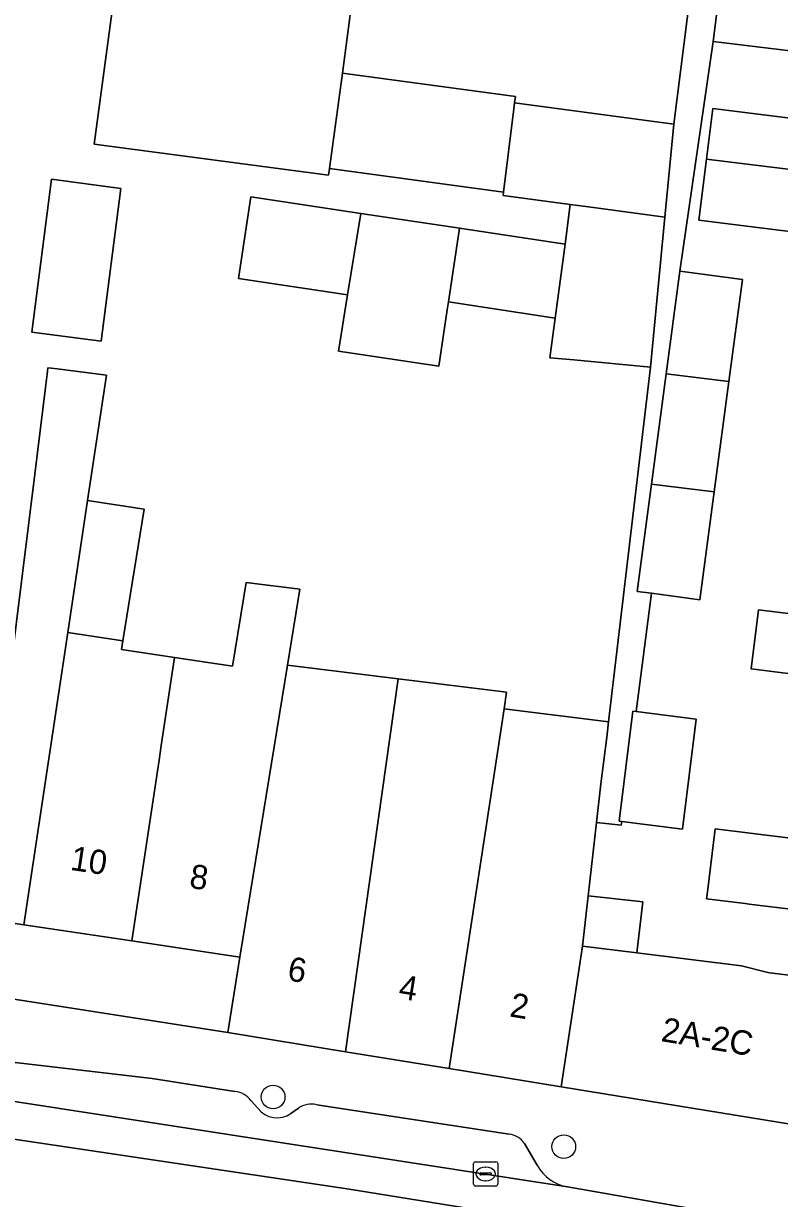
# Model space of a CAD drawing. Extents: x 162172 to 163187, y 382874 to 383685.
# Drawn here: x 162672.8 to 162704, y 383324.93 to 383373.42 of the extents above; entities that cross this region are included whole.
import ezdxf

# ---------------------------------------------------------------- set-up
doc = ezdxf.new("R2010")
doc.units = 0
for name, color, linetype in [('IMGEO_Boom', 7, 'Continuous'), ('IMGEO_Erf', 7, 'Continuous'), ('IMGEO_Kolk', 7, 'Continuous'), ('IMGEO_Pand', 7, 'Continuous'), ('IMGEO_Pand_nummerreeks', 7, 'Continuous'), ('IMGEO_Parkeervlak_open', 7, 'Continuous'), ('IMGEO_Rijbaan_lokaal_gesloten', 7, 'Continuous'), ('IMGEO_Voetpad_open', 7, 'Continuous')]:
    doc.layers.add(name, color=color, linetype=linetype)

msp = doc.modelspace()

# ---------------------------------------------------------------- linework, layer by layer
at = {"layer": 'IMGEO_Boom'}
for centre in [(162683.101, 383329.122), (162695.098, 383327.073)]:
    msp.add_circle(centre, 0.489, dxfattribs=at)
at = {"layer": 'IMGEO_Erf'}
for points in [[(162686.382, 383374.516), (162685.957, 383371.365), (162693.103, 383370.401), (162693.069, 383370.149), (162699.635, 383369.263), (162703.655, 383401.01)], [(162672.244, 383346.619), (162673.262, 383354.819), (162673.706, 383358.396), (162673.775, 383358.952), (162673.807, 383359.209), (162673.954, 383359.191), (162674.187, 383359.162), (162676.222, 383358.91), (162675.443, 383353.731), (162677.778, 383353.38), (162676.899, 383347.94), (162676.843, 383347.588), (162679.03, 383347.259), (162681.428, 383346.899), (162681.989, 383350.35), (162684.2, 383350.076), (162683.69, 383346.942), (162688.256, 383346.377), (162692.738, 383345.821), (162692.634, 383345.142), (162696.946, 383344.607), (162698.677, 383359.232), (162695.514, 383359.534), (162694.528, 383359.628), (162694.745, 383361.264), (162690.335, 383361.927), (162690.286, 383361.6), (162689.937, 383359.278), (162685.799, 383359.901), (162686.176, 383362.219), (162681.666, 383362.897), (162682.173, 383366.265), (162686.722, 383365.581), (162690.793, 383364.969), (162695.15, 383364.314), (162695.367, 383365.95), (162692.593, 383366.322), (162692.61, 383366.459), (162685.425, 383367.428), (162685.388, 383367.153), (162675.713, 383368.44), (162676.707, 383375.803)], [(162704.444, 383372.285), (162701.266, 383372.681), (162699.889, 383363.201), (162702.479, 383362.855), (162701.917, 383358.645), (162701.309, 383354.088), (162700.716, 383349.639), (162698.724, 383349.905), (162698.085, 383345.025), (162700.562, 383344.718), (162699.999, 383340.178), (162697.49, 383340.489), (162697.471, 383340.34), (162696.452, 383340.455), (162696.109, 383337.425), (162698.356, 383337.171), (162698.119, 383335.067), (162702.438, 383334.532), (162703.526, 383334.261), (162703.606, 383334.251), (162704.721, 383334.113)], [(162707.625, 383364.439), (162700.678, 383365.299), (162700.991, 383367.821), (162701.249, 383369.907), (162708.196, 383369.046)], [(162705.449, 383346.46), (162702.837, 383346.784), (162703.139, 383349.225), (162705.482, 383348.935)], [(162625.697, 383340.429), (162681.225, 383331.781), (162681.73, 383334.89), (162677.27, 383335.561), (162672.811, 383336.231), (162668.35, 383336.902)], [(162704.802, 383336.825), (162702.75, 383337.08), (162702.589, 383337.1), (162700.988, 383337.299), (162701.024, 383337.584), (162701.346, 383340.184), (162704.35, 383339.812)]]:
    msp.add_lwpolyline(points, dxfattribs=at)
msp.add_lwpolyline([(162675.996, 383360.304), (162673.135, 383360.677), (162673.958, 383366.988), (162676.819, 383366.615)], close=True, dxfattribs=at)
at = {"layer": 'IMGEO_Kolk'}
for p, q in [((162691.372, 383325.523), (162691.372, 383326.375)), ((162691.447, 383326.449), (162692.299, 383326.449)), ((162691.86, 383326.229), (162691.885, 383326.229)), ((162692.373, 383326.375), (162692.373, 383325.523)), ((162691.631, 383325.943), (162691.631, 383325.955)), ((162692.069, 383325.906), (162691.671, 383325.906)), ((162691.674, 383325.992), (162692.072, 383325.992)), ((162691.883, 383325.669), (162691.858, 383325.669)), ((162692.115, 383325.955), (162692.115, 383325.943)), ((162692.299, 383325.449), (162691.447, 383325.449))]:
    msp.add_line(p, q, dxfattribs=at)
for points in [[(162691.372, 383325.523), (162691.372, 383326.375)], [(162691.447, 383326.449), (162692.299, 383326.449)], [(162692.373, 383326.375), (162692.373, 383325.523)], [(162692.299, 383325.449), (162691.447, 383325.449)]]:
    msp.add_lwpolyline(points, dxfattribs=at)
for centre, radius, start, end in [((162691.449, 383326.373), 0.0765, 91.552, 178.448), ((162691.449, 383326.373), 0.0765, 91.552, 178.448), ((162692.297, 383326.373), 0.0765, 1.552, 88.448), ((162692.297, 383326.373), 0.0765, 1.552, 88.448), ((162691.671, 383325.952), 0.0403, 85.8775, 175.7526), ((162691.668, 383325.942), 0.0366, 178.938, 274.7102), ((162692.072, 383325.949), 0.043, 264.8664, 352.4533), ((162692.076, 383325.954), 0.0386, 1.7309, 96.639), ((162691.449, 383325.525), 0.0765, 181.552, 268.448), ((162691.449, 383325.525), 0.0765, 181.552, 268.448), ((162692.297, 383325.525), 0.0765, 271.552, 358.448), ((162692.297, 383325.525), 0.0765, 271.552, 358.448)]:
    msp.add_arc(centre, radius, start, end, dxfattribs=at)
for centre, major_axis, ratio, start_param, end_param in [((162691.859, 383325.949), (-0.387, 0.002), 0.722429, 4.712389, 7.853982), ((162691.884, 383325.949), (-0.39, 0.002), 0.717154, 1.570796, 4.712389)]:
    msp.add_ellipse(centre, major_axis=major_axis, ratio=ratio, start_param=start_param, end_param=end_param, dxfattribs=at)
at = {"layer": 'IMGEO_Pand'}
for points in [[(162705.022, 383376.787), (162701.827, 383377.183), (162701.266, 383372.681), (162704.444, 383372.285)], [(162686.382, 383374.516), (162676.707, 383375.803), (162675.713, 383368.44), (162685.388, 383367.153), (162685.425, 383367.428), (162685.957, 383371.365)], [(162693.035, 383369.894), (162693.069, 383370.149), (162693.103, 383370.401), (162685.957, 383371.365), (162685.425, 383367.428), (162692.61, 383366.459)], [(162699.635, 383369.263), (162693.069, 383370.149), (162693.035, 383369.894), (162692.61, 383366.459), (162692.593, 383366.322), (162695.367, 383365.95), (162696.118, 383365.849), (162699.269, 383365.427)], [(162708.196, 383369.046), (162701.249, 383369.907), (162700.991, 383367.821), (162707.937, 383366.96)], [(162707.937, 383366.96), (162700.991, 383367.821), (162700.678, 383365.299), (162707.625, 383364.439)], [(162676.819, 383366.615), (162673.958, 383366.988), (162673.135, 383360.677), (162675.996, 383360.304)], [(162686.176, 383362.219), (162686.722, 383365.581), (162682.173, 383366.265), (162681.666, 383362.897)], [(162699.269, 383365.427), (162696.118, 383365.849), (162695.367, 383365.95), (162695.15, 383364.314), (162694.745, 383361.264), (162694.528, 383359.628), (162695.514, 383359.534), (162698.677, 383359.232)], [(162690.793, 383364.969), (162686.722, 383365.581), (162686.176, 383362.219), (162685.799, 383359.901), (162689.937, 383359.278), (162690.286, 383361.6), (162690.335, 383361.927)], [(162690.793, 383364.969), (162690.335, 383361.927), (162694.745, 383361.264), (162695.15, 383364.314)], [(162701.917, 383358.645), (162702.479, 383362.855), (162699.889, 383363.201), (162699.324, 383358.966)], [(162674.624, 383348.282), (162675.443, 383353.731), (162676.222, 383358.91), (162674.187, 383359.162), (162673.954, 383359.191), (162673.807, 383359.209), (162673.775, 383358.952), (162673.706, 383358.396), (162673.262, 383354.819), (162672.244, 383346.619), (162671.969, 383346.653), (162669.856, 383346.915), (162669.592, 383345.16), (162669.553, 383344.9), (162668.35, 383336.902), (162672.811, 383336.231)], [(162701.917, 383358.645), (162699.324, 383358.966), (162698.716, 383354.41), (162701.309, 383354.088)], [(162701.309, 383354.088), (162698.716, 383354.41), (162698.125, 383349.985), (162698.724, 383349.905), (162700.716, 383349.639)], [(162675.443, 383353.731), (162674.624, 383348.282), (162676.899, 383347.94), (162677.778, 383353.38)], [(162683.69, 383346.942), (162684.2, 383350.076), (162681.989, 383350.35), (162681.428, 383346.899), (162679.03, 383347.259), (162678.484, 383343.629), (162678.392, 383343.018), (162677.27, 383335.561), (162681.73, 383334.89)], [(162705.752, 383348.902), (162705.482, 383348.935), (162703.139, 383349.225), (162702.837, 383346.784), (162705.449, 383346.46)], [(162679.03, 383347.259), (162676.843, 383347.588), (162676.899, 383347.94), (162674.624, 383348.282), (162672.811, 383336.231), (162677.27, 383335.561), (162678.392, 383343.018), (162678.484, 383343.629)], [(162687.76, 383342.866), (162688.256, 383346.377), (162683.69, 383346.942), (162681.73, 383334.89), (162681.225, 383331.781), (162686.082, 383330.991)], [(162692.538, 383344.51), (162692.634, 383345.142), (162692.738, 383345.821), (162688.256, 383346.377), (162687.76, 383342.866), (162686.082, 383330.991), (162690.373, 383330.294)], [(162696.109, 383337.425), (162696.452, 383340.455), (162696.631, 383342.038), (162696.871, 383343.972), (162696.946, 383344.607), (162692.634, 383345.142), (162692.538, 383344.51), (162690.373, 383330.294), (162694.994, 383329.543), (162695.874, 383335.345)], [(162698.085, 383345.025), (162697.944, 383345.042), (162697.382, 383340.502), (162697.49, 383340.489), (162699.999, 383340.178), (162700.562, 383344.718)], [(162718.231, 383338.092), (162704.35, 383339.812), (162701.346, 383340.184), (162701.024, 383337.584), (162700.988, 383337.299), (162702.589, 383337.1), (162702.75, 383337.08), (162704.802, 383336.825), (162704.5, 383334.393), (162704.751, 383334.352), (162705.436, 383334.24), (162713.487, 383332.918), (162718.117, 383337.17)], [(162696.109, 383337.425), (162695.874, 383335.345), (162698.119, 383335.067), (162698.356, 383337.171)], [(162704.751, 383334.352), (162704.721, 383334.113), (162703.606, 383334.251), (162703.526, 383334.261), (162702.438, 383334.532), (162698.119, 383335.067), (162695.874, 383335.345), (162694.994, 383329.543), (162707.584, 383327.496), (162713.487, 383332.918), (162705.436, 383334.24)]]:
    msp.add_lwpolyline(points, close=True, dxfattribs=at)
at = {"layer": 'IMGEO_Parkeervlak_open'}
for points in [[(162681.525, 383329.352), (162678.105, 383329.885), (162671.858, 383330.613), (162670.982, 383330.717), (162670.498, 383330.752)], [(162667.234, 383329.74), (162695.256, 383325.416)], [(162682.469, 383328.656), (162682.19, 383328.964)], [(162684.143, 383328.656), (162683.834, 383328.444)], [(162692.84, 383327.592), (162684.899, 383328.802)], [(162693.997, 383326.305), (162693.476, 383327.202)]]:
    msp.add_lwpolyline(points, dxfattribs=at)
for centre, radius, start, end in [((162681.424, 383328.415), 0.942, 35.6204, 83.856), ((162683.263, 383329.267), 1.001, 217.5668, 304.7769), ((162684.675, 383327.93), 0.9, 75.6064, 126.2545), ((162692.71, 383326.667), 0.934, 34.9515, 82.0146), ((162695.567, 383327.192), 1.803, 209.4704, 260.0765)]:
    msp.add_arc(centre, radius, start, end, dxfattribs=at)
at = {"layer": 'IMGEO_Rijbaan_lokaal_gesloten'}
for points in [[(162701.209, 383324.364), (162695.256, 383325.416), (162667.234, 383329.74), (162654.358, 383331.729), (162650.713, 383332.282), (162613.69, 383338.058), (162613.319, 383338.115), (162605.204, 383339.371), (162601.788, 383339.9), (162574.971, 383344.078), (162574.184, 383344.194), (162573.598, 383344.329), (162573.305, 383344.396)], [(162759.102, 383279.436), (162751.245, 383288.934), (162744.614, 383296.969), (162741.887, 383300.164), (162738.772, 383303.437), (162735.656, 383306.164), (162728.412, 383311.307), (162722.803, 383314.892), (162719.766, 383316.606), (162716.105, 383318.242), (162707.381, 383321.359), (162706.089, 383321.777), (162704.23, 383322.378), (162698.267, 383323.385), (162686.155, 383325.334), (162667.305, 383328.139), (162627.21, 383334.45)], [(162627.21, 383334.45), (162667.305, 383328.139), (162686.155, 383325.334), (162698.267, 383323.385), (162704.23, 383322.378), (162706.089, 383321.777), (162707.381, 383321.359), (162716.105, 383318.242), (162719.766, 383316.606), (162722.803, 383314.892), (162728.412, 383311.307), (162735.656, 383306.164), (162738.772, 383303.437), (162741.887, 383300.164), (162744.614, 383296.969), (162751.245, 383288.934), (162759.102, 383279.436)]]:
    msp.add_lwpolyline(points, dxfattribs=at)
at = {"layer": 'IMGEO_Voetpad_open'}
for points in [[(162703.655, 383401.01), (162699.635, 383369.263), (162699.269, 383365.427), (162698.677, 383359.232), (162696.946, 383344.607), (162696.871, 383343.972), (162696.631, 383342.038), (162696.452, 383340.455), (162697.471, 383340.34), (162697.49, 383340.489), (162697.382, 383340.502), (162697.944, 383345.042), (162698.085, 383345.025), (162698.724, 383349.905), (162698.125, 383349.985), (162698.716, 383354.41), (162699.324, 383358.966), (162699.889, 383363.201), (162701.266, 383372.681), (162701.827, 383377.183)], [(162707.156, 383322.944), (162707.317, 383323.417), (162714.458, 383320.909), (162714.598, 383324.993), (162710.992, 383326.273), (162707.584, 383327.496), (162694.994, 383329.543), (162690.373, 383330.294), (162686.082, 383330.991), (162681.225, 383331.781), (162625.697, 383340.429)], [(162670.498, 383330.752), (162670.982, 383330.717), (162671.858, 383330.613), (162678.105, 383329.885), (162681.525, 383329.352)], [(162682.19, 383328.964), (162682.469, 383328.656)], [(162683.834, 383328.444), (162684.143, 383328.656)], [(162684.899, 383328.802), (162692.84, 383327.592)], [(162693.476, 383327.202), (162693.997, 383326.305)], [(162695.256, 383325.416), (162701.209, 383324.364)]]:
    msp.add_lwpolyline(points, dxfattribs=at)
for centre, radius, start, end in [((162681.424, 383328.415), 0.942, 35.6204, 83.856), ((162683.263, 383329.267), 1.001, 217.5668, 304.7769), ((162684.675, 383327.93), 0.9, 75.6064, 126.2545), ((162692.71, 383326.667), 0.934, 34.9515, 82.0146), ((162695.567, 383327.192), 1.803, 209.4704, 260.0765)]:
    msp.add_arc(centre, radius, start, end, dxfattribs=at)

# ---------------------------------------------------------------- texts
at = {"layer": 'IMGEO_Pand_nummerreeks'}
for s, rotation, p in [('10', 351.4457, (162674.692, 383338.498)), ('8', 351.4457, (162679.606, 383337.758)), ('6', 350.7696, (162683.652, 383333.94)), ('4', 350.7696, (162688.242, 383333.194)), ('2', 350.7696, (162692.829, 383332.448)), ('2A-2C', 350.5061, (162699.08, 383331.431))]:
    msp.add_text(s, height=1, rotation=rotation, dxfattribs=at).set_placement(p)

doc.saveas('drawing.dxf')
